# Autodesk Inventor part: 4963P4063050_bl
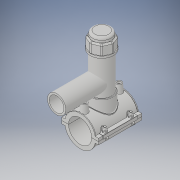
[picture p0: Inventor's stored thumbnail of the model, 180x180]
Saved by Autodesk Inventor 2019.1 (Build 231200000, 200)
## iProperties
Created: 2017-07
Part Number: 4963P4063050_bl
Material: Generic
Document SubType Name: Modeling
Designer: KIM
Density: 1 g/cm^3
Appearance: Default
Author: KIM
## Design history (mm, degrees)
derived "4963P4.ipt"
feature "Solid1::4963P4.ipt" dims "ScaleForDerivedMember" = 10
feature "Solid2::4963P4.ipt" dims "ScaleForDerivedMember" = 10
feature "Solid3::4963P4.ipt" dims "ScaleForDerivedMember" = 10
tag "TaggingFeature1"
body "Solid1"
body "Solid2"
body "Solid3"
other parameters: "d0" = 63 [user parameter], "d3" = 15.75 [user parameter], "d4" = 118 [user parameter], "d5" = 0 [user parameter], "d6" = 0.1 [user parameter], "d8" = 0 [user parameter], "d19" = 6 [user parameter], "d20" = 6 [user parameter], "d21" = 70.8 [user parameter], "d23" = 0 [user parameter], "d24" = 35.4 [user parameter], "d26" = 0 [user parameter], "d27" = 3 [user parameter], "d28" = 3 [user parameter], "d29" = 3 [user parameter], "d30" = 21 [user parameter], "d31" = 6 [user parameter], "d32" = 0 [user parameter], "d33" = 0 [user parameter], "d34" = 0.6 [user parameter], "d40" = 42.588 [user parameter], "d41" = 63 [user parameter], "d43" = 0 [user parameter], "d45" = 0 [user parameter], "d47" = 111.75 [user parameter], "d70" = 15 [user parameter], "d72" = 0 [user parameter], "d73" = 6 [user parameter], "d75" = 5 [user parameter], "d76" = 0 [user parameter], "d77" = 3.15 [user parameter], "d78" = 61.5 [user parameter], "d79" = 15 [user parameter], "d80" = 47.2 [user parameter], "d82" = 5 deg [user parameter], "d84" = 4 [user parameter], "d85" = 14 [user parameter], "d86" = 0 [user parameter], "d87" = 3 [user parameter], "d88" = 0 [user parameter], "d89" = 1 [user parameter], "d90" = 1 [user parameter], "d91" = 94.4 [user parameter], "d92" = 0 [user parameter], "d93" = 0.5 [user parameter], "d94" = 33.15789 [user parameter], "d96" = 83.538 [user parameter], "d97" = 2.36 [user parameter], "d98" = 0 [user parameter], "d102" = 0.63 [user parameter], "d120" = 140 deg [user parameter], "d121" = 24.228 [user parameter], "d122" = 20 deg [user parameter], "d123" = 163.8 [user parameter], "d124" = 49.14 [user parameter], "d126" = 0 [user parameter], "d143" = 64.89 [user parameter], "d145" = 14.53846 [user parameter], "d149" = 0.945 [user parameter], "d150" = 15.99231 [user parameter], "d153" = 118 [user parameter], "d154" = 0 [user parameter], "d156" = 40.95 [user parameter], "d157" = 160 deg [user parameter], "d159" = 3.78 [user parameter], "d161" = 0.945 [user parameter], "d162" = 70.8 [user parameter], "d163" = 0 [user parameter], "d164" = 31.5 [user parameter], "d167" = 6.3 [user parameter], "d168" = 39.95122 [user parameter], "d170" = 3.75 [user parameter], "d172" = 0 [user parameter], "d173" = 1 [user parameter], "d175" = 31.5 [user parameter], "d176" = 20 deg [user parameter], "d177" = 4.41 [user parameter], "d178" = 18.9 [user parameter], "d180" = 0 [user parameter], "d183" = 7.56 [user parameter], "d184" = 3.528 [user parameter], "d185" = 38.35 [user parameter], "d186" = 38.35 [user parameter], "d187" = 40.95 [user parameter], "d188" = 5.67 [user parameter], "d189" = 4.41 [user parameter], "d190" = 0 [user parameter], "d191" = 61.425 [user parameter], "d193" = 8 [user parameter], "d194" = 4.13 [user parameter], "d195" = 90 deg [user parameter], "d197" = 0 [user parameter], "d199" = 0 [user parameter], "d200" = 9.45 [user parameter], "d202" = 0 [user parameter], "d203" = 177 [user parameter], "d204" = 59.85 [user parameter], "d205" = 44.1 [user parameter], "d206" = 53.55 [user parameter], "d207" = 132.75 [user parameter], "d208" = 138.06 [user parameter], "d209" = 164.61 [user parameter], "d210" = 54.18 [user parameter], "d211" = 63 [user parameter], "d212" = 50.4 [user parameter], "d213" = 35.1 [user parameter], "d216" = 0 [user parameter], "d217" = 6.3 [user parameter], "d218" = 6.3 [user parameter], "d219" = 1.26 [user parameter], "d222" = 63 [user parameter], "d224" = 0 [user parameter], "d225" = 64 [user parameter], "d228" = 123 [user parameter], "d230" = 3.78 [user parameter], "d_" = 63 [user parameter], "L_" = 118 [user parameter], "d_t" = 6 [user parameter], "H_2" = 177 [user parameter], "H_1" = 64 [user parameter]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
